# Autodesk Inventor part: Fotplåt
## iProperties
Created: 2001-12
Part Number: Fotplåt
Material: S235JRG2
Document SubType Name: Modeling
Designer: Tobben
Control State: 0
Master: False
Checked Out: False
Shininess: 64.0
Length Units: 11269
Angle Units: 11279
Time Units: 11290
Mass Units: 11283
Length Display Precision: 3
Angle Display Precision: 2
Compacted: True
Density: 0.0
Volumn: 0.0
Area: 0.0
PropertySet Name: Model Information
Author: Tobben
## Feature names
1. Extrusion1
2. Extrusion2
